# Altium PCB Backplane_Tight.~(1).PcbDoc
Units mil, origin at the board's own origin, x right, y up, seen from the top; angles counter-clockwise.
Board outline 6520 x 1500 mil, 6 copper layers (Top Layer, DGND, +5V, AGND, VCC, Bottom Layer), stack 50.76 mil thick; 22 components, 84 nets, 241 pads, 4 vias.
Unrouted connection lines stored in the file: 28.
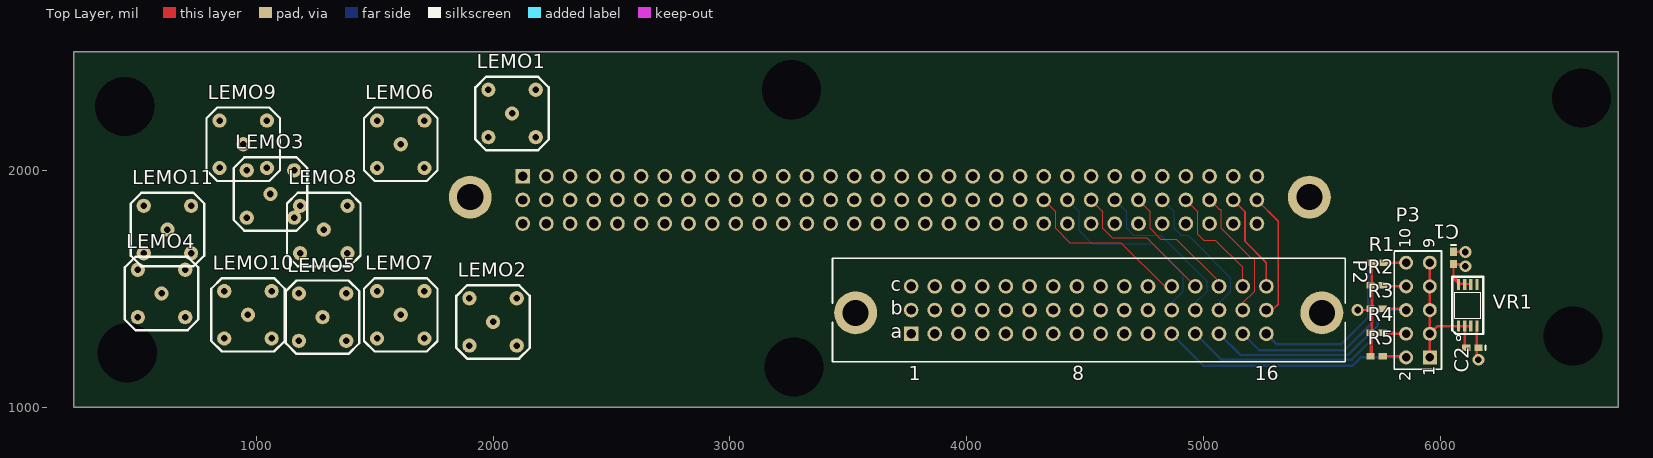
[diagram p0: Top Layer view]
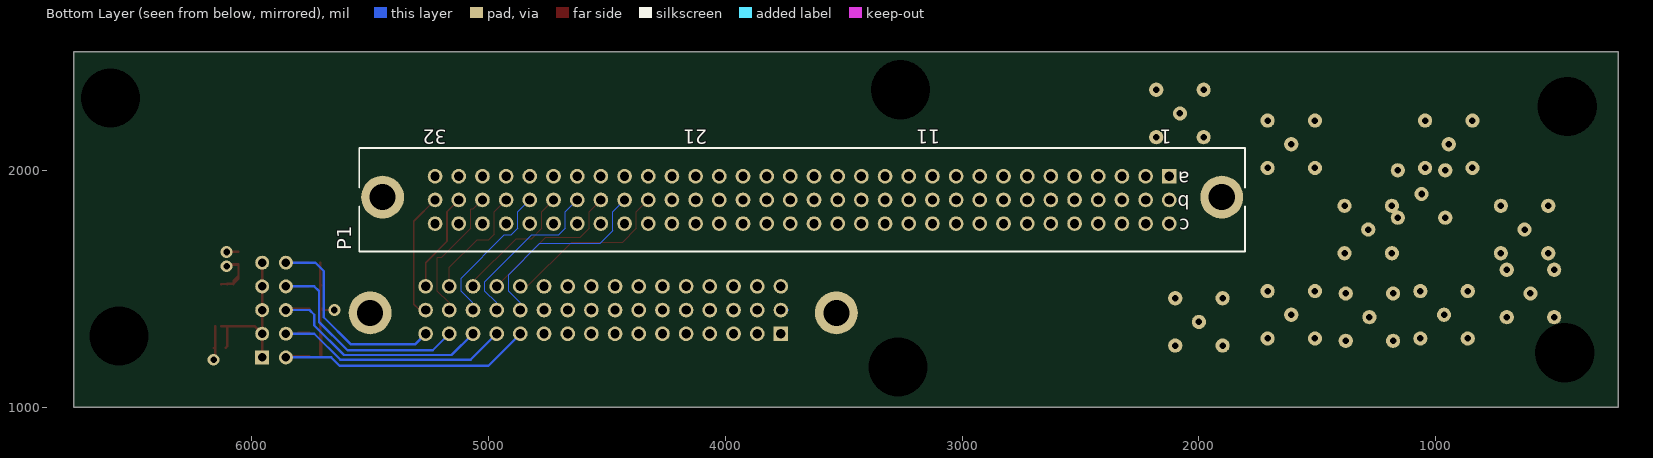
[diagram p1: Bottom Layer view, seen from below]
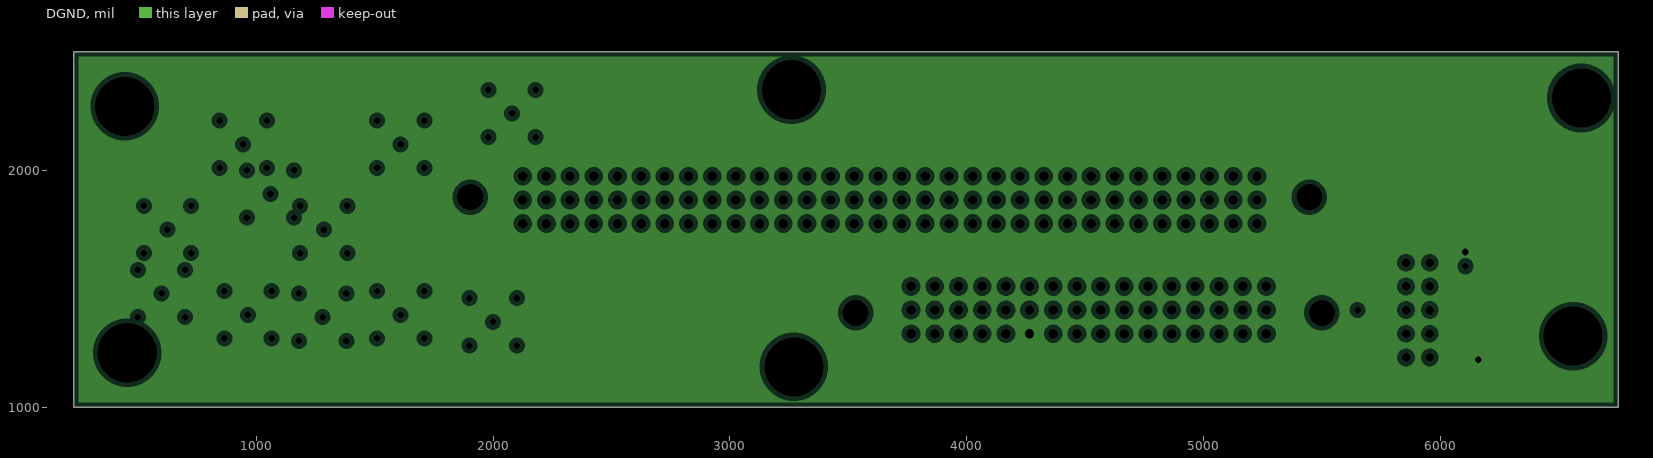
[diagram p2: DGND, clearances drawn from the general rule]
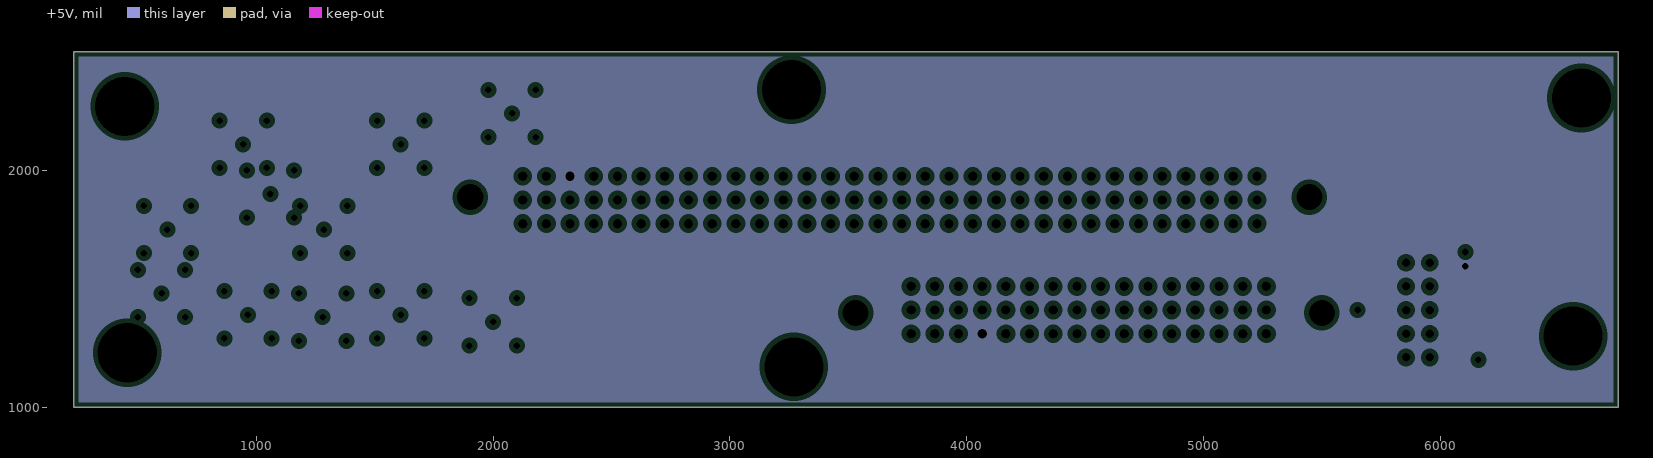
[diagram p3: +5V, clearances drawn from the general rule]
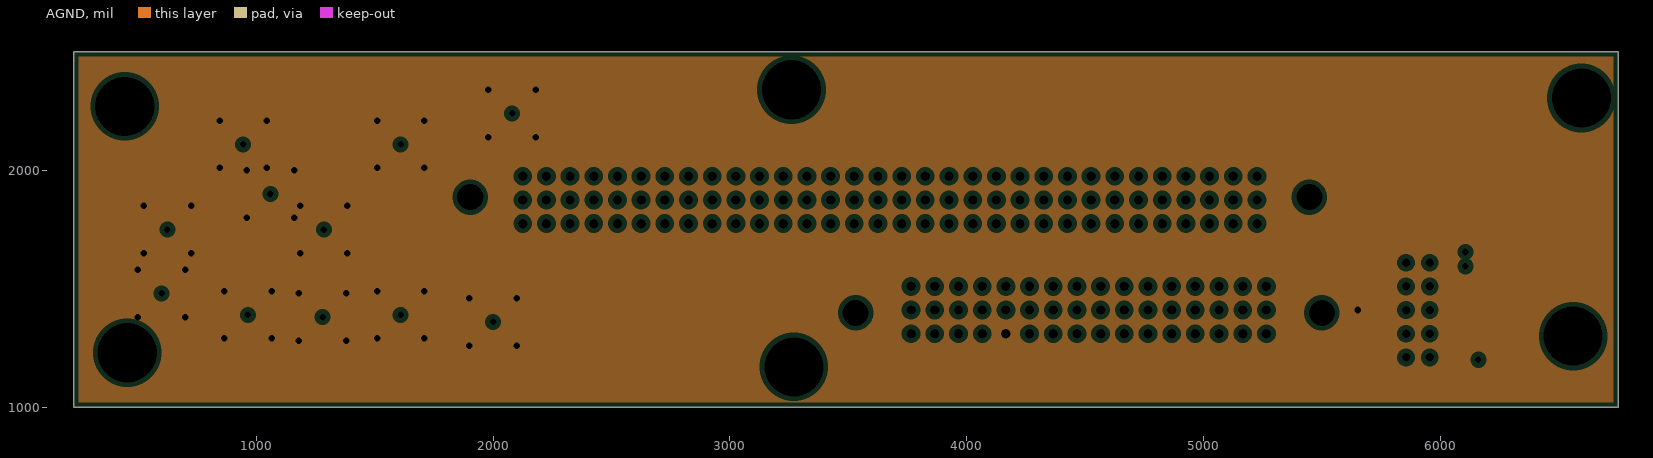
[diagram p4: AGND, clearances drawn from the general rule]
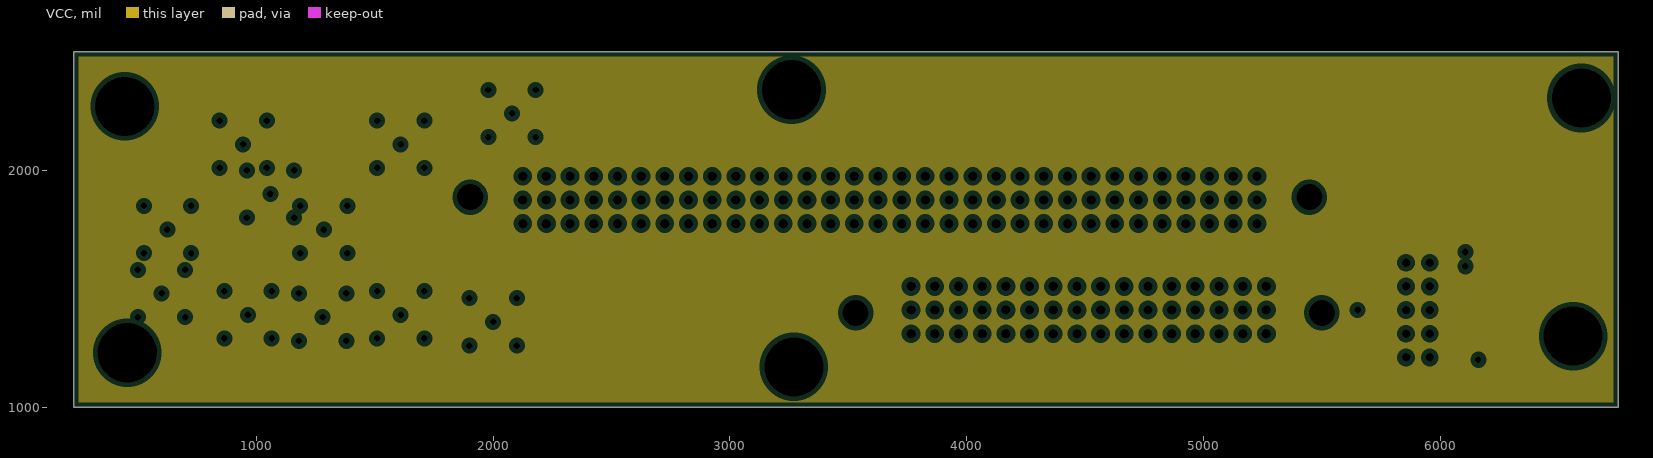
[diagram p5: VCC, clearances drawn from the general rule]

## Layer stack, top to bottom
Top Layer: signal copper 1.4
Dielectric: prepreg 5.1, FR-4, Dk 4.8
DGND: plane copper 1.4, net DGND
Dielectric: core 10.72, FR-4, Dk 4.8
+5V: plane copper 1.4, net +5V
Dielectric: prepreg 10.72, FR-4, Dk 4.8
AGND: plane copper 1.4, net AGND
Dielectric: core 10.72, FR-4, Dk 4.8
VCC: plane copper 1.4
Dielectric: prepreg 5.1, FR-4, Dk 4.8
Bottom Layer: signal copper 1.4

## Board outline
230,1000 6750,1000 6750,2500 230,2500

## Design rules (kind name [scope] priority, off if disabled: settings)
Clearance Clearance_BIAS [InNetClass('BIAS')] p1: gap=15
Clearance [All] p2: gap=10
ComponentClearance [All] p1: gap=10 collisioncheckmode=3 verticalgap=10
PlaneClearance [All] p1: clearance=20
PlaneConnect [All] p1: planeconnectstyle=Relief reliefexpansion=20 reliefentries=4 reliefconductorwidth=10 reliefairgap=10
PolygonConnect [All] p1: connectstyle=Relief reliefconductorwidth=10 reliefentries=4 polygonreliefangle="90 Angle"
RoomDefinition LEMO [InComponentClass('LEMO')] p1: confinementstyle=ConfineIn formatcopy=TRUE lockcomponents=FALSE outline 275,1060 4885,1060 4885,2460 275,2460
RoomDefinition "Digital Connector" [InComponentClass('Digital Connector')] p2: confinementstyle=ConfineIn formatcopy=TRUE lockcomponents=FALSE outline 3170,1085 6595,1085 6595,1895 3170,1895
RoomDefinition "Analog Connector" [InComponentClass('Analog Connector')] p3: confinementstyle=ConfineIn formatcopy=TRUE lockcomponents=FALSE outline 1595,1555 5615,1555 5615,2230 1595,2230
RoutingVias [All] p1: holewidth=28 width=50 viastyle="Through Hole" minholewidth=28 minwidth=50 maxholewidth=28 maxwidth=50
SolderMaskExpansion [All] p1: expansion=4
SupplyNets VCC [OnLayer('VCC')] p1: voltage=10.00
SupplyNets +5V [OnLayer('+5V')] p2: voltage=5.000
SupplyNets DGND [OnLayer(DGND)] p3: voltage=0.000
SupplyNets AGND [OnLayer('AGND')] p4: voltage=0.000
TestPointUsage [All] p1: valid=0 allowmultiple=FALSE
Testpoint [All] p1: side=15 testpointundercomponent=TRUE minsize=40 maxsize=100 preferedsize=60 minholesize=0 maxholesize=40 preferedholesize=32 testpointgrid=1 style=1023 order=0-112345678
Width [All] p1: maxlimit=10 minlimit=5 preferedwidth=7
Width Width_BIAS [InNetClass('BIAS')] p2: maxlimit=10 minlimit=4 preferedwidth=5
Width Width_SIPMOUT [InNetClass('SIPMOUT')] p3: maxlimit=7.35 minlimit=2.1 preferedwidth=7.35 impedancedriven=TRUE minimp=50.000000 maximp=80.000000 favimp=50.000000
16 further rules are at their usual default settings.

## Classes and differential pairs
component class "Analog Connector": P1
component class "Digital Connector": C1 C2 P2 P3 R1 R2 R3 R4 R5 R? VR1
component class LEMO: LEMO1 LEMO2 LEMO3 LEMO4 LEMO5 LEMO6 LEMO7 LEMO8 LEMO9 LEMO10 LEMO11
net class BIAS: SIPMBIAS1 SIPMBIAS2 SIPMBIAS3 SIPMBIAS4 SIPMBIAS5 SIPMBIAS6 SIPMBIAS7 SIPMBIAS8 SIPMBIAS9 SIPMBIAS10 SIPMBIAS11 SIPMBIAS12 SIPMBIAS13 SIPMBIAS14 SIPMBIAS15 SIPMBIAS16 SIPMBIAS17 SIPMBIAS18 SIPMBIAS19 SIPMBIAS20 SIPMBIAS21 SIPMBIAS22 SIPMBIAS23 SIPMBIAS24 SIPMBIAS25 SIPMBIAS26 SIPMBIAS27 SIPMBIAS28 SIPMBIAS29 SIPMBIAS30 SIPMBIAS31 SIPMBIAS32
net class SIPMOUT: SIPMOUT1 SIPMOUT2 SIPMOUT3 SIPMOUT4 SIPMOUT5 SIPMOUT6 SIPMOUT7 SIPMOUT8 SIPMOUT9 SIPMOUT10 SIPMOUT11 SIPMOUT12 SIPMOUT13 SIPMOUT14 SIPMOUT15 SIPMOUT16 SIPMOUT17 SIPMOUT18 SIPMOUT19 SIPMOUT20 SIPMOUT21 SIPMOUT22 SIPMOUT23 SIPMOUT24 SIPMOUT25 SIPMOUT26 SIPMOUT27 SIPMOUT28 SIPMOUT29 SIPMOUT30 SIPMOUT31 SIPMOUT32 SUMMED1 SUMMED2 SUMMED3 SUMMED4 SUMMED5 SUMMED6

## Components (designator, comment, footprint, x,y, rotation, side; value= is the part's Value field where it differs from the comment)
C1 "Kemet C0402C104K8PACTU" 0402 6055,1630 r270 top
C2 "Kemet C1206C106K9PACTU" 0402 6135,1250 r180 top
LEMO1 "LEMO EPA.00" "LEMO EPA.00" 2080,2240 r0 top
LEMO2 "LEMO EPA.00" "LEMO EPA.00" 2000,1360 r0 top
LEMO3 "LEMO EPA.00" "LEMO EPA.00" 1060,1900 r0 top
LEMO4 "LEMO EPA.00" "LEMO EPA.00" 600,1480 r0 top
LEMO5 "LEMO EPA.00" "LEMO EPA.00" 1280,1380 r0 top
LEMO6 "LEMO EPA.00" "LEMO EPA.00" 1610,2110 r0 top
LEMO7 "LEMO EPA.00" "LEMO EPA.00" 1610,1390 r0 top
LEMO8 "LEMO EPA.00" "LEMO EPA.00" 1285,1750 r0 top
LEMO9 "LEMO EPA.00" "LEMO EPA.00" 945,2110 r0 top
LEMO10 "LEMO EPA.00" "LEMO EPA.00" 965,1390 r0 top
LEMO11 "LEMO EPA.00" "LEMO EPA.00" 625,1750 r0 top
P1 "DIN41612 96 pin, Backplane" EURO2.54-2V96 3675,1875 r0 bottom
P2 "DIN41612 48 pin, Backplane" EURO2.54-2V48 4515,1410 r0 top
P3 "Header 5X2" HDR2X5 5955,1210 r90 top
R1 "Res2" 1005[0402] 5735,1610 r0 top
R2 "Res2" 1005[0402] 5730,1515 r0 top
R3 "Res2" 1005[0402] 5730,1415 r0 top
R4 "Res2" 1005[0402] 5730,1315 r0 top
R5 "Res2" 1005[0402] 5730,1215 r0 top
VR1 "" RM-8 6115,1430 r0 top

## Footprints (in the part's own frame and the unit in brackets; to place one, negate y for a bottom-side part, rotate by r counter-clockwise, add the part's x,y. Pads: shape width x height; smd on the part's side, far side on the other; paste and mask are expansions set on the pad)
0402 [mm] "Chip Capacitor; Body 1.0 x 0.5 mm (LxW typ)"
  rect 0.9x0.7 smd: 1(-0.65,0) 2(0.65,0)
  silkscreen extent -1.4,-0.25 -1.4,0.25
1005[0402] [mm] "Chip Resistor; Body 1.1 x 0.5 mm (LxW typ)"
  rect 0.9x0.7 smd: 1(-0.65,0) 2(0.65,0)
EURO2.54-2V48 [mil] "Connector; DIN 41612, Type 2C, Thru-Hole; Rows a+b+c, 48 Position; Vertical"
  round 181.1 hole 110.24: 17(-984.25,-11.81) 18(984.25,-11.81)
  rect 62x62 hole 39.37: A1(-750,-100)
  round 62 hole 39.37: A2(-650,-100) A3(-550,-100) A4(-450,-100) A5(-350,-100) A6(-250,-100) A7(-150,-100) A8(-50,-100) A9(50,-100) A10(150,-100) A11(250,-100) A12(350,-100) A13(450,-100) A14(550,-100) A15(650,-100) A16(750,-100) B1(-750,0) B2(-650,0) B3(-550,0) B4(-450,0) B5(-350,0) B6(-250,0) B7(-150,0) B8(-50,0) B9(50,0) B10(150,0) B11(250,0) B12(350,0) B13(450,0) B14(550,0) B15(650,0) B16(750,0) C1(-750,100) C2(-650,100) C3(-550,100) C4(-450,100) C5(-350,100) C6(-250,100) C7(-150,100) C8(-50,100) C9(50,100) C10(150,100) C11(250,100) C12(350,100) C13(450,100) C14(550,100) C15(650,100) C16(750,100)
  silkscreen extent -1083,-219 1083,219
EURO2.54-2V96 [mil] "Connector; DIN 41612, Type C, Thru-Hole; Rows a+b+c, 96 Position; Vertical"
  round 181.1 hole 110.24: 33(-1771.65,-11.81) 34(1771.65,-11.81)
  rect 62x62 hole 39.37: A1(-1550,-100)
  round 62 hole 39.37: A2(-1450,-100) A3(-1350,-100) A4(-1250,-100) A5(-1150,-100) A6(-1050,-100) A7(-950,-100) A8(-850,-100) A9(-750,-100) A10(-650,-100) A11(-550,-100) A12(-450,-100) A13(-350,-100) A14(-250,-100) A15(-150,-100) A16(-50,-100) A17(50,-100) A18(150,-100) A19(250,-100) A20(350,-100) A21(450,-100) A22(550,-100) A23(650,-100) A24(750,-100) A25(850,-100) A26(950,-100) A27(1050,-100) A28(1150,-100) A29(1250,-100) A30(1350,-100) A31(1450,-100) A32(1550,-100) B1(-1550,0) B2(-1450,0) B3(-1350,0) B4(-1250,0) B5(-1150,0) B6(-1050,0) B7(-950,0) B8(-850,0) B9(-750,0) B10(-650,0) B11(-550,0) B12(-450,0) B13(-350,0) B14(-250,0) B15(-150,0) B16(-50,0) B17(50,0) B18(150,0) B19(250,0) B20(350,0) B21(450,0) B22(550,0) B23(650,0) B24(750,0) B25(850,0) B26(950,0) B27(1050,0) B28(1150,0) B29(1250,0) B30(1350,0) B31(1450,0) B32(1550,0) C1(-1550,100) C2(-1450,100) C3(-1350,100) C4(-1250,100) C5(-1150,100) C6(-1050,100) C7(-950,100) C8(-850,100) C9(-750,100) C10(-650,100) C11(-550,100) C12(-450,100) C13(-350,100) C14(-250,100) C15(-150,100) C16(-50,100) C17(50,100) C18(150,100) C19(250,100) C20(350,100) C21(450,100) C22(550,100) C23(650,100) C24(750,100) C25(850,100) C26(950,100) C27(1050,100) C28(1150,100) C29(1250,100) C30(1350,100) C31(1450,100) C32(1550,100)
  silkscreen extent -1870,-219 1870,219
HDR2X5 [mm] "Connector; Header; 5x2 Position"
  rect 1.5x1.5 hole 0.9: 1(0,0)
  round 1.5 hole 0.9: 2(0,2.54) 3(2.54,0) 4(2.54,2.54) 5(5.08,0) 6(5.08,2.54) 7(7.62,0) 8(7.62,2.54) 9(10.16,0) 10(10.16,2.54)
  silkscreen extent -1.27,-1.27 11.43,3.81
"LEMO EPA.00" [mil]
  round 60 hole 27.56: 0(0,0) 1(-100,100) 2(100,100) 3(100,-100) 4(-100,-100)
  silkscreen extent -155,-155 155,155
RM-8 [mil]
  rect 13.4x46.9 smd: 1(-38.6,-87.8) 2(-12.6,-87.8) 3(12.6,-87.8) 4(38.6,-87.8) 5(38.6,87.8) 6(12.6,87.8) 7(-12.6,87.8) 8(-38.6,87.8)
  silkscreen extent -65,-148 65,121

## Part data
C1 C2: library part Cap, "Capacitor"
P3: "Header, 5-Pin, Dual row"
R1 R2 R3 R4 R5: "Resistor"
VR1: library part ADP3335

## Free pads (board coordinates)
  round 60 hole 250: 0(445,2270) 0(455,1230) 0(3260,2340) 0(3270,1170) 0(6560,1300) 0(6595,2305)

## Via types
v1: diameter 50, hole 28, Top Layer to Bottom Layer, 4 vias

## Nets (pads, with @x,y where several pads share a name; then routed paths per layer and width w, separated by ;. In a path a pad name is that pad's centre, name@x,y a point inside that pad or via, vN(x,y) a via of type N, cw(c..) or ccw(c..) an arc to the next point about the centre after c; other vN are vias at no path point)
+3.3V: C2.2 P3.1 P3.3 P3.5 P3.7 P3.9 VR1.1 VR1.2 VR1.3 | length 681
  Top Layer w10: P3.1 P3.3 ; P3.9 P3.7 P3.5 P3.3 ; C2.2 6102.4,1257.01 VR1.2 ; VR1.3 VR1.2 ; P3.3 5987.2,1342.2 VR1.1 VR1.2
+5V: C1.2 P1.A3 P2.A4 VR1.6 VR1.7 VR1.8 | length 470.4
  Top Layer w10: VR1.8 VR1.8@6076.4,1521 ; VR1.7 VR1.7@6102.4,1520 ; v1(6105,1595) v1@6100,1600 ; VR1.6 VR1.6@6127.6,1520 ; 6055,1554.4 6076.4,1533 VR1.8@6076.4,1522.2 ; 6055,1554.4 6055,1543.6 VR1.8@6076.4,1522.2 ; 6055,1554.4 C1.2@6055,1600 ; C1.2@6055,1600 v1@6100,1600 ; C1.2@6055,1600 C1.2 6095.59,1604.41 v1@6100,1600 ; C1.2@6055,1600 v1@6100,1600 ; VR1.8@6076.4,1521 VR1.8@6077.6,1521 ; VR1.8@6076.4,1521 VR1.8@6076.4,1522.2 ; VR1.8@6076.4,1521 VR1.8@6077.6,1521 ; VR1.8@6076.4,1522.2 VR1.8@6077.6,1521 ; VR1.8@6077.6,1521 VR1.8@6078.6,1520 ; VR1.8@6077.6,1521 VR1.7@6102.4,1521 ; VR1.8@6077.6,1521 VR1.7@6102.4,1521 ; VR1.8@6077.6,1521 VR1.8@6078.6,1520 ; VR1.8@6078.6,1520 VR1.7@6102.4,1520 ; VR1.8@6078.6,1520 VR1.7@6102.4,1520 ; v1@6100,1600 v1@6105,1600 ; v1@6100,1600 v1@6105,1600 ; VR1.7@6102.4,1520 VR1.6@6127.6,1520 ; VR1.7@6102.4,1520 VR1.7@6102.4,1521 ; VR1.7@6102.4,1520 VR1.6@6127.6,1520 ; v1@6105,1600 6115,1600 v1@6105,1600
+210V: P2.A2
-5V: P2.A3
ADC_EXT1: P2.A7
ADC_EXT2: P2.A8
AGND: LEMO1.1 LEMO1.2 LEMO1.3 LEMO1.4 LEMO2.1 LEMO2.2 LEMO2.3 LEMO2.4 LEMO3.1 LEMO3.2 LEMO3.3 LEMO3.4 LEMO4.1 LEMO4.2 LEMO4.3 LEMO4.4 LEMO5.1 LEMO5.2 LEMO5.3 LEMO5.4 LEMO6.1 LEMO6.2 LEMO6.3 LEMO6.4 LEMO7.1 LEMO7.2 LEMO7.3 LEMO7.4 LEMO8.1 LEMO8.2 LEMO8.3 LEMO8.4 LEMO9.1 LEMO9.2 LEMO9.3 LEMO9.4 LEMO10.1 LEMO10.2 LEMO10.3 LEMO10.4 LEMO11.1 LEMO11.2 LEMO11.3 LEMO11.4 P2.A5 R1.1 R2.1 R3.1 R4.1 R5.1 | length 1259.6
  Top Layer w10: v1(5650,1410) R3.1@5699.41,1410 ; R5.1 R5.1@5705,1215 ; R4.1 R4.1@5705,1315 ; R2.1 R2.1@5709,1515 ; R3.1@5699.41,1410 R3.1@5699.41,1415 ; R3.1@5699.41,1410 R3.1@5699.41,1415 ; R3.1@5699.41,1415 R3.1 R3.1@5709,1415 ; R5.1@5705,1215 R4.1@5705,1315 ; R5.1@5705,1215 R4.1@5705,1315 ; R4.1@5705,1315 R4.1@5709.41,1315 ; R3.1@5709,1415 R2.1@5709,1515 ; R3.1@5709,1415 R2.1@5709,1515 ; R2.1@5709,1515 R2.1@5709.41,1515 ; R4.1@5709.41,1315 5709.41,1220 R4.1@5709.41,1315 ; R4.1@5709.41,1315 R3.1@5709.41,1415 ; R4.1@5709.41,1315 R3.1@5709.41,1415 ; R3.1@5709.41,1415 R2.1@5709.41,1515 ; R3.1@5709.41,1415 R2.1@5709.41,1515 ; R2.1@5709.41,1515 R1.1 R2.1@5709.41,1515
CP2201/LA: P2.A1
DGND: C1.1 C2.1 P2.A6 VR1.4 | length 337.9
  Top Layer w10: C1.1 6104.41,1655.59 v1(6105,1655) ; v1(6160,1200) v1@6153.6,1206.4 ; C2.1 C2.1@6153.6,1250 ; v1@6153.6,1206.4 C2.1@6153.6,1250 ; v1@6153.6,1206.4 C2.1@6153.6,1250 ; C2.1@6153.6,1250 VR1.4 C2.1@6153.6,1250
ID0: P2.A16 P3.10 R1.2 | length 960.2
  Top Layer w10: R1.2 P3.10
  Bottom Layer w10: P2.A16 5310,1265 5580,1265 5695,1380 5695,1575 5730,1610 P3.10
ID1: P2.A15 P3.8 R2.2 | length 1001.4
  Top Layer w10: R2.2@5760.59,1510 P3.8
  Bottom Layer w10: P2.A15 5235,1240 5595,1240 5715,1360 5715,1490 5735,1510 P3.8
ID2: P2.A14 P3.6 R3.2 | length 1136.2
  Top Layer w10: P3.6 P3.6@5855,1415 ; P3.6@5855,1415 R3.2 P3.6@5855,1415
  Bottom Layer w10: P2.A14 5155,1220 5610,1220 5735,1345 5735,1390 5755,1410 P3.6
ID3: P2.A13 P3.4 R4.2 | length 1129
  Top Layer w10: R4.2 5802,1315 5807,1310 ; R4.2@5760.59,1310 5807,1310 ; P3.4 5807,1310
  Bottom Layer w10: P2.A13 5075,1200 5625,1200 5735,1310 P3.4
ID4: P2.A12 P3.2 R5.2 | length 1264.2
  Top Layer w10: P3.2 P3.2@5855,1215 ; P3.2@5855,1215 R5.2 P3.2@5855,1215
  Bottom Layer w10: P2.A12 5000,1175 5628.28,1175 5663.28,1210 P3.2
SIPMBIAS1: P1.B1 P2.C1
SIPMBIAS2: P1.B2 P2.B1 | length 40
  Bottom Layer w5: P2.B1@3765,1415 P2.B1 P2.B1@3770,1410
  Bottom Layer w10: P2.B1@3735,1410 P2.B1
SIPMBIAS3: P1.B3 P2.C2
SIPMBIAS4: P1.B4 P2.B2 | length 5
  Bottom Layer w5: P2.B2 P2.B2@3865,1415
SIPMBIAS5: P1.B5 P2.C3 | length 25
  Bottom Layer w5: P2.C3 P2.C3@3965,1535
SIPMBIAS6: P1.B6 P2.B3 | length 10
  Bottom Layer w5: P2.B3 P2.B3@3975,1410
SIPMBIAS7: P1.B7 P2.C4
SIPMBIAS8: P1.B8 P2.B4 | length 10
  Bottom Layer w5: P2.B4 P2.B4@4065,1420
SIPMBIAS9: P1.B9 P2.C5
SIPMBIAS10: P1.B10 P2.B5
SIPMBIAS11: P1.B11 P2.C6
SIPMBIAS12: P1.B12 P2.B6 | length 20
  Bottom Layer w5: P2.B6 P2.B6@4265,1430
SIPMBIAS13: P1.B13 P2.C7
SIPMBIAS14: P1.B14 P2.B7 | length 5
  Bottom Layer w5: P2.B7 P2.B7@4370,1410
SIPMBIAS15: P1.B15 P2.C8
SIPMBIAS16: P1.B16 P2.B8 | length 5
  Bottom Layer w5: P2.B8 P2.B8@4470,1410
SIPMBIAS17: P1.B17 P2.C9
SIPMBIAS18: P1.B18 P2.B9 | length 5
  Bottom Layer w5: P2.B9 P2.B9@4565,1415
SIPMBIAS19: P1.B19 P2.C10
SIPMBIAS20: P1.B20 P2.B10 | length 10
  Bottom Layer w5: P2.B10 P2.B10@4675,1410
SIPMBIAS21: P1.B21 P2.C11
SIPMBIAS22: P1.B22 P2.B11 | length 5
  Bottom Layer w5: P2.B11 P2.B11@4765,1415
SIPMBIAS23: P1.B23 P2.C12 | length 732.2
  Top Layer w5: P1.B23 4375,1825 4375,1755 4435,1695 4650,1695 4835,1510 P2.C12
SIPMBIAS24: P1.B24 P2.B12 | length 838.1
  Bottom Layer w5: P1.B24 4475,1825 4475,1745 4530,1690 4785,1690 4915,1560 4915,1490 4865,1440 P2.B12
SIPMBIAS25: P1.B25 P2.C13 | length 639.3
  Top Layer w5: P1.B25@4520,1880 4575,1825 4575,1755 4615,1715 4760,1715 P2.C13
SIPMBIAS26: P1.B26 P2.B13 | length 724.6
  Bottom Layer w5: P1.B26 4675,1825 4675,1755 4705,1725 4820,1725 5015,1530 5015,1490 4965,1440 P2.B13 P2.B13@4975,1410
SIPMBIAS27: P1.B27 P2.C14 | length 543.9
  Top Layer w5: P1.B27 4775,1825 4775,1755 4820,1710 4885,1710 5065,1530 P2.C14
SIPMBIAS28: P1.B28 P2.B14 | length 628.4
  Bottom Layer w5: P1.B28 4875,1825 4875,1755 4905,1725 4935,1725 5115,1545 5115,1490 5065,1440 P2.B14 P2.B14@5070,1410
SIPMBIAS29: P1.B29 P2.C15 | length 518.7
  Top Layer w5: P1.B29 4975,1825 4975,1730 5000,1705 5050,1705 5165,1590 P2.C15
  Bottom Layer w5: P2.C15 P2.C15@5165,1535
SIPMBIAS30: P1.B30 P2.B15 | length 589.1
  Top Layer w5: P1.B30 5065,1835 5075,1835 5075,1755 5200,1630 5215,1630 5215,1490 5165,1440 P2.B15
  Bottom Layer w5: P2.B15 P2.B15@5175,1410
SIPMBIAS31: P1.B31 P2.C16 | length 423
  Top Layer w7: P1.B31 5175,1825 5175,1700 5265,1610 P2.C16
SIPMBIAS32: P1.B32 P2.B16 | length 545.6
  Top Layer w7: P1.B32 5315,1785 5315,1435 5295,1415 P2.B16@5255,1415
SIPMOUT1: P1.C1
SIPMOUT2: P1.C2
SIPMOUT3: P1.C3
SIPMOUT4: P1.C4
SIPMOUT5: P1.C5
SIPMOUT6: P1.C6
SIPMOUT7: P1.C7
SIPMOUT8: P1.C8
SIPMOUT9: P1.C9
SIPMOUT10: P1.C10
SIPMOUT11: P1.C11
SIPMOUT12: P1.C12
SIPMOUT13: P1.C13
SIPMOUT14: P1.C14
SIPMOUT15: P1.C15
SIPMOUT16: P1.C16
SIPMOUT17: P1.C17
SIPMOUT18: P1.C18
SIPMOUT19: P1.C19
SIPMOUT20: P1.C20
SIPMOUT21: P1.C21
SIPMOUT22: P1.C22
SIPMOUT23: P1.C23
SIPMOUT24: P1.C24
SIPMOUT25: P1.C25
SIPMOUT26: P1.C26
SIPMOUT27: P1.C27
SIPMOUT28: P1.C28
SIPMOUT29: P1.C29
SIPMOUT30: P1.C30
SIPMOUT31: P1.C31
SIPMOUT32: P1.C32
SUMMED1: LEMO1.0 P1.A1
SUMMED2: LEMO2.0 P1.A6
SUMMED3: LEMO3.0 P1.A11
SUMMED4: LEMO4.0 P1.A16
SUMMED5: LEMO5.0 P1.A21
SUMMED6: LEMO6.0 P1.A26
pads on no net: LEMO7.0 LEMO8.0 LEMO9.0 LEMO10.0 LEMO11.0 P1.33 P1.34 P1.A2 P1.A4 P1.A5 P1.A7 P1.A8 P1.A9 P1.A10 P1.A12 P1.A13 P1.A14 P1.A15 P1.A17 P1.A18 P1.A19 P1.A20 P1.A22 P1.A23 P1.A24 P1.A25 P1.A27 P1.A28 P1.A29 P1.A30 P1.A31 P1.A32 P2.17 P2.18 P2.A9 P2.A10 P2.A11 VR1.5

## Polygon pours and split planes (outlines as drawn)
DGND on DGND (split plane): 6729.61,1020.39 250.39,1020.39 250.39,2479.61 6729.61,2479.61
AGND on AGND (split plane): 6729.61,1020.39 250.39,1020.39 250.39,2479.61 6729.61,2479.61
+5V on +5V (split plane): 6729.61,1020.39 250.39,1020.39 250.39,2479.61 6729.61,2479.61
no net on VCC (split plane): 6729.61,1020.39 250.39,1020.39 250.39,2479.61 6729.61,2479.61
